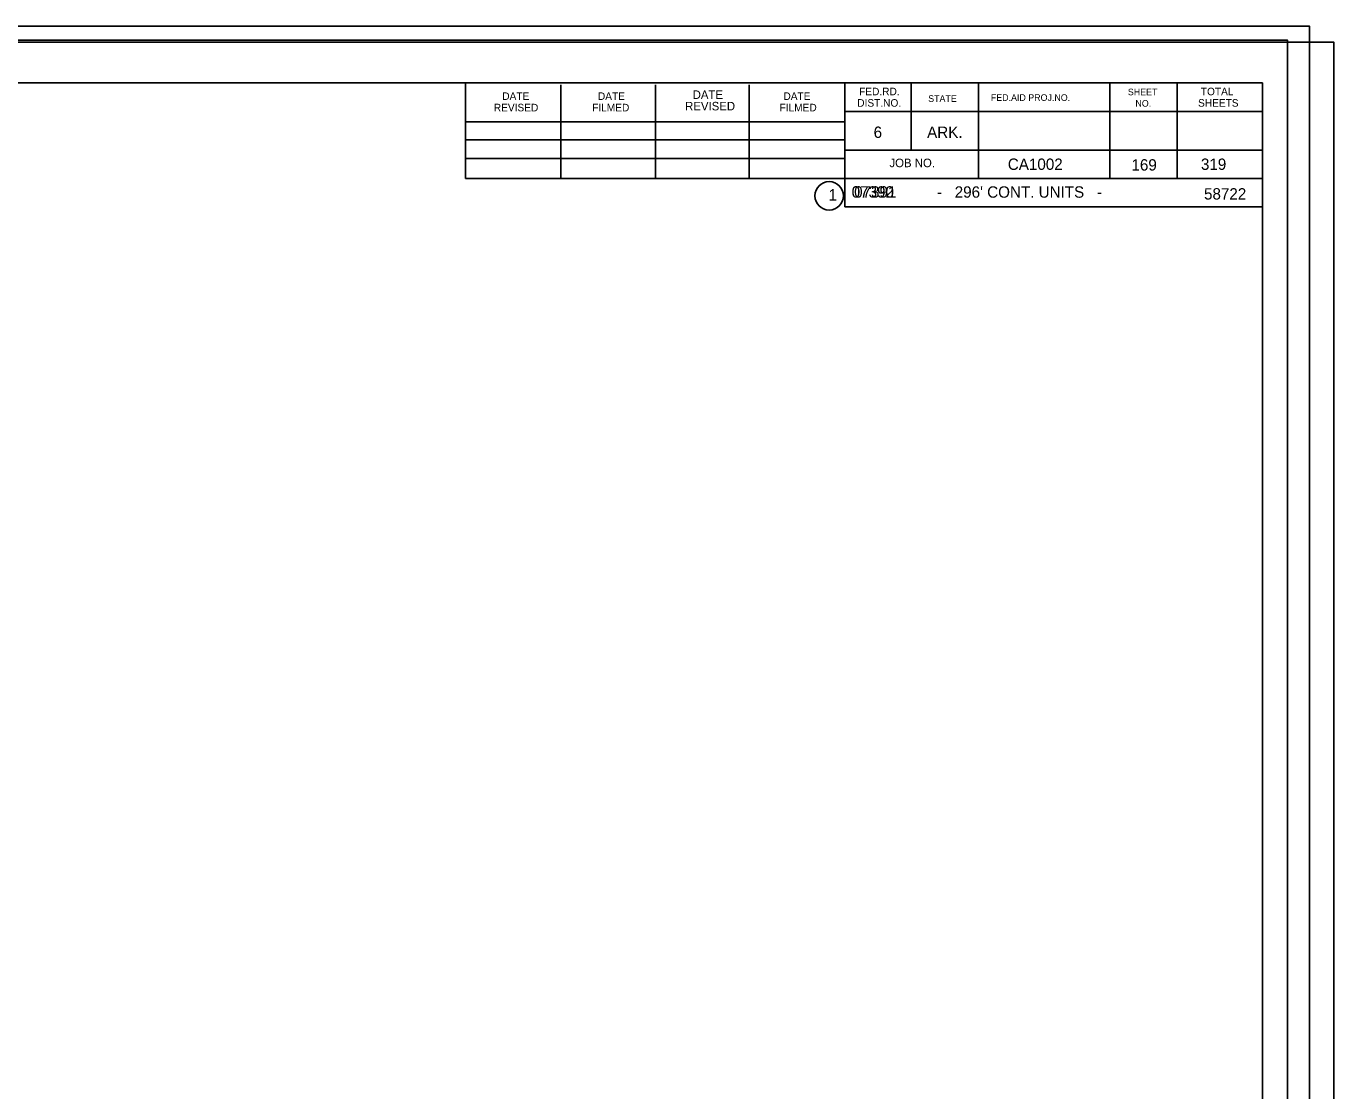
# Model space of a CAD drawing. Extents: x -1771525.9 to -1771483.9, y -422628.9 to -422606.9.
# Drawn here: x -1771504.92 to -1771491.42, y -422617.89 to -422606.91 of the extents above; entities that cross this region are included whole.
import ezdxf

# ---------------------------------------------------------------- set-up
doc = ezdxf.new("R2010")
doc.units = 0
for name, color, linetype in [('border', 7, 'Continuous'), ('Border 2660-Hwy18 - Level 62', 7, 'Continuous'), ('Border 2660-Hwy18 - Level 63', 7, 'Continuous'), ('Border 2660-Hwy18 - Text', 7, 'Continuous'), ('Bridge No BLFR', 7, 'Continuous'), ('Bridge No BLO', 7, 'Continuous'), ('Bridge No Ditch 81', 7, 'Continuous'), ('Level 62 PDF', 7, 'Continuous'), ('Text', 7, 'Continuous'), ('Title Text', 7, 'Continuous')]:
    doc.layers.add(name, color=color, linetype=linetype)

msp = doc.modelspace()

# ---------------------------------------------------------------- linework, layer by layer
at = {"layer": 'border'}
for p, q in [((-1771524.168, -422607.492), (-1771492.157, -422607.492)), ((-1771500.383, -422608.48), (-1771500.383, -422607.492)), ((-1771499.398, -422608.48), (-1771499.398, -422607.512)), ((-1771498.421, -422608.48), (-1771498.421, -422607.512)), ((-1771497.454, -422608.48), (-1771497.454, -422607.512)), ((-1771496.468, -422607.492), (-1771496.468, -422608.772)), ((-1771495.784, -422607.492), (-1771495.784, -422608.186)), ((-1771495.089, -422607.492), (-1771495.089, -422608.48)), ((-1771493.732, -422607.492), (-1771493.732, -422608.48)), ((-1771493.037, -422607.492), (-1771493.037, -422608.48)), ((-1771492.157, -422628.038), (-1771492.157, -422607.492)), ((-1771492.157, -422607.786), (-1771496.468, -422607.786)), ((-1771492.157, -422607.784), (-1771492.157, -422607.784)), ((-1771500.383, -422607.894), (-1771496.468, -422607.894)), ((-1771500.383, -422608.08), (-1771496.468, -422608.08)), ((-1771500.383, -422608.48), (-1771500.383, -422608.274)), ((-1771500.383, -422608.274), (-1771496.468, -422608.274)), ((-1771492.157, -422608.186), (-1771496.468, -422608.186)), ((-1771496.171, -422608.186), (-1771492.157, -422608.186)), ((-1771492.157, -422608.48), (-1771500.383, -422608.48)), ((-1771496.468, -422608.772), (-1771492.157, -422608.772))]:
    msp.add_line(p, q, dxfattribs=at)
msp.add_circle((-1771496.629, -422608.658), 0.147, dxfattribs=at)
at = {"layer": 'Border 2660-Hwy18 - Level 62'}
msp.add_lwpolyline([(-1771525.789, -422606.907), (-1771491.67, -422606.907), (-1771491.67, -422628.716), (-1771525.789, -422628.716)], close=True, dxfattribs=at)
at = {"layer": 'Border 2660-Hwy18 - Level 63'}
msp.add_lwpolyline([(-1771525.9, -422607.05), (-1771491.9, -422607.05), (-1771491.9, -422628.419), (-1771525.9, -422628.419)], close=True, dxfattribs=at)
at = {"layer": 'Level 62 PDF'}
msp.add_lwpolyline([(-1771525.539, -422607.073), (-1771491.42, -422607.073), (-1771491.42, -422628.883), (-1771525.539, -422628.883)], close=True, dxfattribs=at)

# ---------------------------------------------------------------- texts
at = {"layer": 'Border 2660-Hwy18 - Text'}
for s, height, p in [('DATE', 0.0782, (-1771500.003, -422607.668)), ('DATE', 0.0782, (-1771499.016, -422607.668)), ('DATE', 0.0879, (-1771498.038, -422607.658)), ('DATE', 0.0782, (-1771497.101, -422607.668)), ('FED.RD.', 0.0782, (-1771496.32, -422607.62)), ('SHEET', 0.0684, (-1771493.546, -422607.62)), ('TOTAL', 0.0782, (-1771492.793, -422607.62)), ('REVISED', 0.0782, (-1771500.09, -422607.786)), ('FILMED', 0.0782, (-1771499.075, -422607.786)), ('REVISED', 0.0879, (-1771498.116, -422607.776)), ('FILMED', 0.0782, (-1771497.141, -422607.786)), ('DIST.NO.', 0.0782, (-1771496.339, -422607.738)), ('STATE', 0.0684, (-1771495.607, -422607.688)), ('FED.AID PROJ.NO.', 0.06839, (-1771494.96, -422607.678)), ('NO.', 0.0684, (-1771493.468, -422607.738)), ('SHEETS', 0.0782, (-1771492.822, -422607.738)), ('6', 0.117, (-1771496.17, -422608.06)), ('ARK.', 0.1172, (-1771495.618, -422608.06)), ('JOB NO.', 0.0879, (-1771496.007, -422608.362)), ('CA1002', 0.1172, (-1771494.785, -422608.39)), ('319', 0.1172, (-1771492.792, -422608.39)), ('1', 0.117, (-1771496.636, -422608.706))]:
    msp.add_text(s, height=height, dxfattribs=at).set_placement(p)
at = {"layer": 'Bridge No BLFR'}
msp.add_text('07392', height=0.1172, dxfattribs=at).set_placement((-1771496.397, -422608.676))
at = {"layer": 'Bridge No BLO'}
msp.add_text('07391', height=0.1172, dxfattribs=at).set_placement((-1771496.371, -422608.676))
at = {"layer": 'Bridge No Ditch 81'}
msp.add_text('07390', height=0.1172, dxfattribs=at).set_placement((-1771496.396, -422608.676))
at = {"layer": 'Text'}
msp.add_text('169', height=0.1172, dxfattribs=at).set_placement((-1771493.509, -422608.397))
at = {"layer": 'Title Text'}
for s, height, p in [("-   296' CONT. UNITS   -", 0.11722, (-1771495.516, -422608.677)), ('58722', 0.1172, (-1771492.76, -422608.696))]:
    msp.add_text(s, height=height, dxfattribs=at).set_placement(p)

doc.saveas('drawing.dxf')
